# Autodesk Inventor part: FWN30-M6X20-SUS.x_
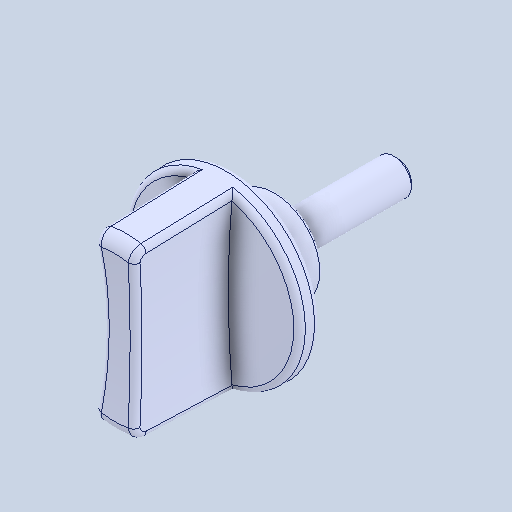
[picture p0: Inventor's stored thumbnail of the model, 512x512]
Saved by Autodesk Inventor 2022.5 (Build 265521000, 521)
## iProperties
Created: 2024-05
Part Number: FWN30-M6X20-SUS.x_
Material: 一般
Document SubType Name: Modeling
Designer: ImaoCorp
Density: 1 g/cm^3
Appearance: 既定
Author: ImaoCorp
Sending System: SOLIDWORKS 2022-2022290
MC: AMD64
MC_MODEL: Intel64 Family 6 Model 60 Stepping 3, GenuineIntel
OS: Windows_NT
FRU: Parasolid Version 33.1, build 260,  4-25-2022
FORMAT: text
GUISE: transmit
KEY: FILEFWN30-M6X20-SUS.x_t
DATE: Mon May 20 16:40:37 2024
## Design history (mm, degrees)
feature "Base1"
node "ソリッド1"
